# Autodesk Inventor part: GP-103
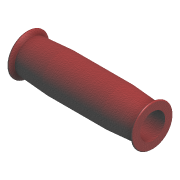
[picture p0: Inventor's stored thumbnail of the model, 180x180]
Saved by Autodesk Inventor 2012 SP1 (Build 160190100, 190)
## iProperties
Shininess: 0.0
Length Units: 11269
Angle Units: 11279
Time Units: 11290
Mass Units: 11283
Length Display Precision: 3
Angle Display Precision: 2
Compacted: True
Created: 2000-09
Part Number: GP-103
Description: SOFFOAM GRIP
Vendor: REID TOOL
Document SubType Name: Modeling
Designer: Ron
Density: 1 g/cm^3
Material: Default
Density: 0.0
Volumn: 0.0
Area: 0.0
PropertySet Name: Model Information
Control State: 0
Master: False
Checked Out: False
Author: Ron
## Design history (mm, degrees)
node "Revolution1" dims "d7" = 90 deg
  sketch "Sketch1"
    geometry: L1 (0, 0)-(0, 7); L2 (1.866, 7.467)-(3.8, 3.841); L3 (3.8, 3.841)-(33.5, 6); L4 (33.5, 6)-(63.5, 6); L5 (63.5, 6)-(63.5, 0); L6 (63.5, 0)-(0, 0); L7 (-1.555, -12.7)-(27.605, -12.7); A1 r 0.991 centre (0.991, 7) between (1.866, 7.467) and (0, 7); 1 further point
    constraints: 14 end point, 2 parallel, 2 perpendicular, 2 point on circle, 2 tangent, 1 centre point, 1 coincident, 1 vertical
    dimensions: "d0" = 25.4 diameter of L6 L7; "d1" = 63.5 distance between parallel lines of L1 L5; "d2" = 6 distance between parallel lines of L4 L6; "d3" = 7 distance from line of A1.centre L6; "d4" = 0.99145 radius of A1; "d5" = 4.15712 deg angle of L3 L4; "d6" = 28.0725 deg angle of L1 L2; "d11" = 30 distance of L3.end L4.end
node "Mirror1"
body "Solid1"
